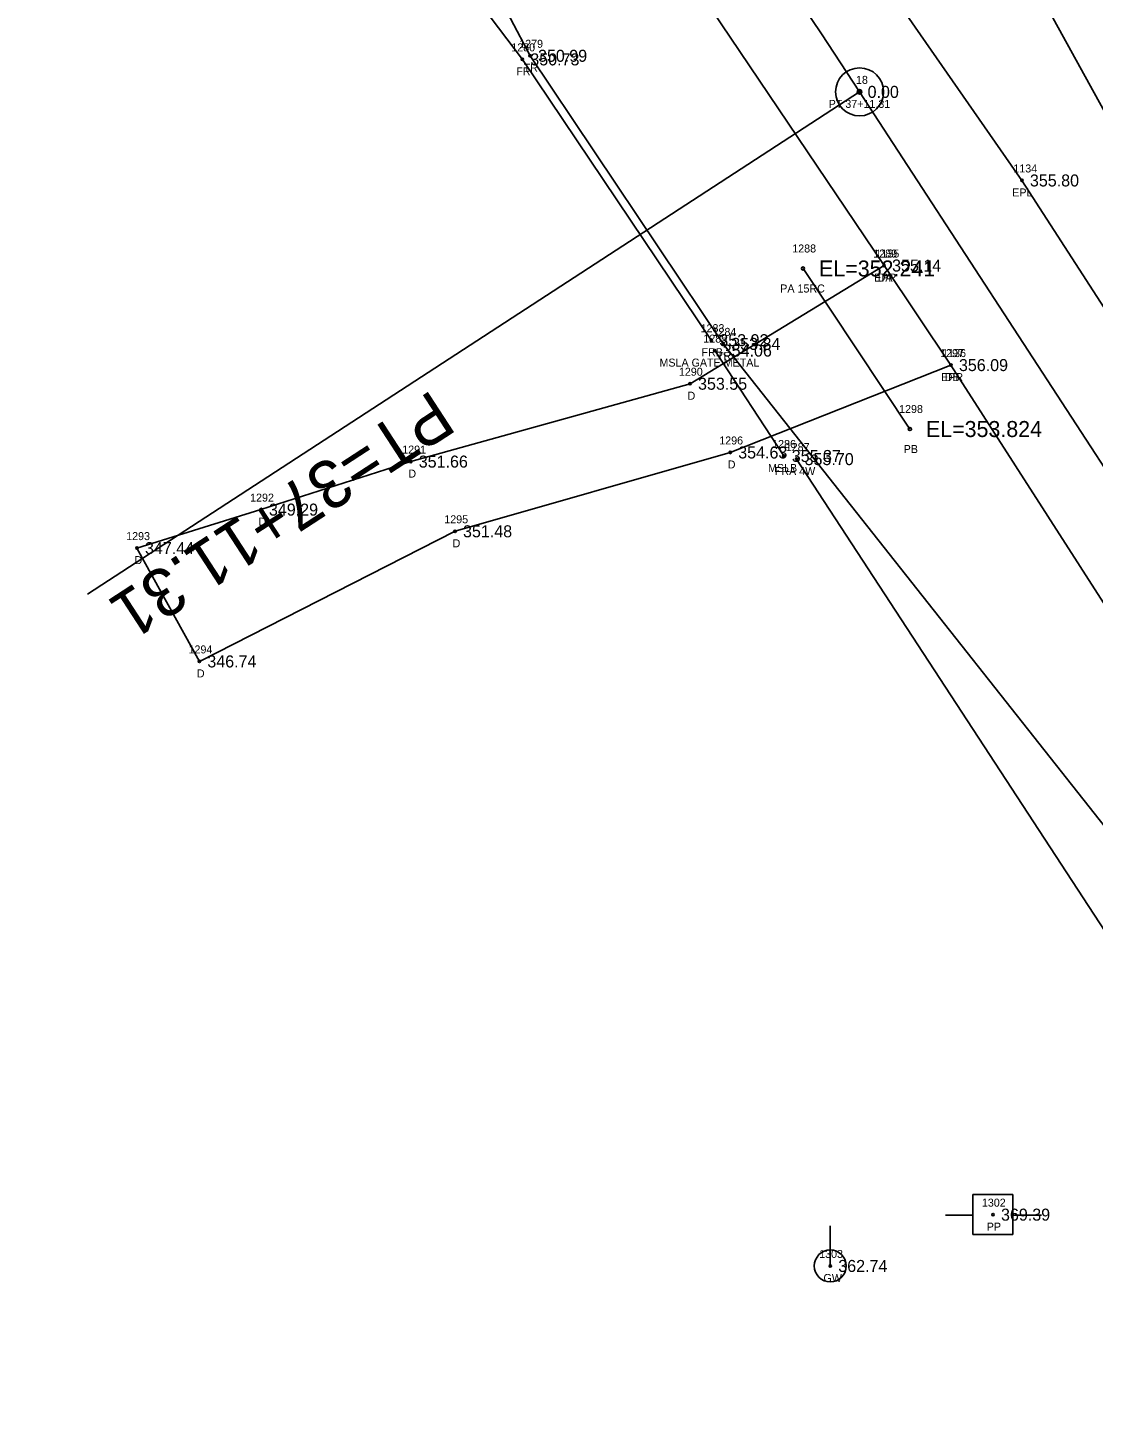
# Model space of a CAD drawing. Extents: x 2006517 to 2008868, y 1001613 to 1004633.
# Drawn here: x 2008072.6 to 2008205.7, y 1002447.7 to 1002622.5 of the extents above; entities that cross this region are included whole.
import ezdxf

# ---------------------------------------------------------------- set-up
doc = ezdxf.new("R2010")
doc.units = 0
for name, color, linetype in [('RD_EX_DR_Pipe', 7, 'Continuous'), ('RD_EX_DR_Pipe_txCode', 7, 'Continuous'), ('RD_EX_Driveway', 7, 'Continuous'), ('RD_EX_Driveway_txCode', 7, 'Continuous'), ('RD_EX_Fence_Other', 7, 'Continuous'), ('RD_EX_Fence_Other_txCode', 7, 'Continuous'), ('RD_EX_Misc', 7, 'Continuous'), ('RD_EX_Misc_txCode', 7, 'Continuous'), ('RD_EX_Road', 7, 'Continuous'), ('RD_EX_Road_txCode', 7, 'Continuous'), ('RD_EX_TX_Driveway_ELEV', 7, 'Continuous'), ('RD_EX_TX_Fence_Other_ELEV', 7, 'Continuous'), ('RD_EX_TX_Misc_ELEV', 7, 'Continuous'), ('RD_EX_TX_Road_ELEV', 7, 'Continuous'), ('RD_EX_TX_UT_ELEV', 7, 'Continuous'), ('RD_EX_TX_VEG_ELEV', 7, 'Continuous'), ('RD_EX_UT', 7, 'Continuous'), ('RD_EX_UT_txCode', 7, 'Continuous'), ('RD_EX_VEG', 7, 'Continuous'), ('RD_EX_VEG_txCode', 7, 'Continuous'), ('RD_HC_Cl', 7, 'Continuous'), ('RD_HC_Data', 7, 'Continuous'), ('RD_HC_Survey_ELEV', 7, 'Continuous'), ('RD_HC_txCode', 7, 'Continuous'), ('RD_SMD_Locator', 7, 'Continuous'), ('RD_TX_Pipe_ElevEX', 7, 'Continuous')]:
    doc.layers.add(name, color=color, linetype=linetype)

msp = doc.modelspace()

# ---------------------------------------------------------------- linework, layer by layer
at = {"layer": 'RD_EX_DR_Pipe'}
msp.add_line((2008169.47, 1002592.48), (2008182.82, 1002572.42), dxfattribs=at)
at = {"layer": 'RD_EX_Driveway'}
msp.add_lwpolyline([(2008179.59, 1002592.85), (2008155.35, 1002578.08), (2008120.46, 1002568.35), (2008101.74, 1002562.35), (2008086.26, 1002557.54), (2008094.05, 1002543.38), (2008125.99, 1002559.64), (2008160.37, 1002569.49), (2008187.94, 1002580.41)], dxfattribs=at)
at = {"layer": 'RD_EX_Fence_Other'}
for points in [[(2007893.11, 1002837.65), (2007909.33, 1002864.32), (2007977.3, 1002793.73), (2008015.3, 1002762.96), (2008043.08, 1002729.4), (2008077.68, 1002692.52), (2008105.37, 1002656.99), (2008134.4, 1002618.61), (2008158.01, 1002583.52)], [(2008168.66, 1002568.66), (2008213.42, 1002500.12), (2008255.13, 1002423.5), (2008299.49, 1002334.35), (2008395.55, 1002139.85)]]:
    msp.add_lwpolyline(points, dxfattribs=at)
at = {"layer": 'RD_EX_Misc'}
msp.add_line((2008158.44, 1002582.22), (2008167.06, 1002569.05), dxfattribs=at)
at = {"layer": 'RD_EX_Road'}
for points in [[(2007926.53, 1002880.46), (2007933.33, 1002888.64), (2008004.37, 1002823.78), (2008041.16, 1002791.39), (2008076.97, 1002755.85), (2008109.64, 1002720.02), (2008140.82, 1002682.03), (2008169.79, 1002642.37), (2008196.81, 1002603.48), (2008249.05, 1002522.64), (2008259.94, 1002505.27), (2008271.29, 1002488.2), (2008299.71, 1002443.6), (2008349.96, 1002366.27), (2008401.09, 1002286.99), (2008453.35, 1002207.39), (2008504.32, 1002128.41), (2008557.14, 1002047.24), (2008604.7, 1001974.22), (2008628.71, 1001937.76), (2008659.22, 1001891.69), (2008712.34, 1001810.72), (2008764.8, 1001729.24), (2008801.79, 1001664.14)], [(2007926.53, 1002880.46), (2007919.41, 1002872.5), (2007991.54, 1002809.35), (2008026.83, 1002776.85), (2008062.37, 1002741.51), (2008093.99, 1002707.06), (2008125.02, 1002669.01), (2008154.41, 1002630.27), (2008179.59, 1002592.85), (2008187.94, 1002580.41), (2008232, 1002511.78), (2008283.05, 1002433.59)]]:
    msp.add_lwpolyline(points, dxfattribs=at)
at = {"layer": 'RD_EX_UT'}
for p, q in [((2008195.69, 1002476.76), (2008190.69, 1002476.76)), ((2008190.69, 1002476.76), (2008190.69, 1002471.76)), ((2008195.69, 1002471.76), (2008195.69, 1002476.76)), ((2008187.26, 1002474.2), (2008190.72, 1002474.2)), ((2008195.61, 1002474.2), (2008199.26, 1002474.2)), ((2008172.87, 1002467.84), (2008172.87, 1002472.84)), ((2008190.69, 1002471.76), (2008195.69, 1002471.76))]:
    msp.add_line(p, q, dxfattribs=at)
msp.add_circle((2008172.87, 1002467.84), 2, dxfattribs=at)
at = {"layer": 'RD_EX_VEG'}
for points in [[(2007395.89, 1003327.12), (2007429.8, 1003285.17), (2007467.04, 1003247.92), (2007498.61, 1003210.85), (2007670.4, 1003045.37), (2007967.56, 1002793.96), (2008054.61, 1002736.66), (2008078.76, 1002693.39), (2008113.28, 1002661.09), (2008135.36, 1002619.06), (2008159.5, 1002583.06), (2008222.5, 1002503.36), (2008272.84, 1002426.91), (2008323.43, 1002347.7), (2008431.42, 1002192), (2008479.95, 1002108.23), (2008533.09, 1002033.28), (2008631.97, 1001873.89), (2008775.08, 1001653.06)], [(2007473.93, 1003322.69), (2007503.07, 1003282.99), (2007540.25, 1003252.05), (2007579.27, 1003219.13), (2007642.18, 1003150.48), (2007952.5, 1002910.4), (2008017.59, 1002836.73), (2008047.98, 1002799.05), (2008087.42, 1002767.09), (2008121.48, 1002729.06), (2008151.49, 1002690.42), (2008185.86, 1002650.76), (2008208.76, 1002609.15), (2008254.04, 1002533.01), (2008311.38, 1002450.28), (2008360.35, 1002372.97), (2008409.06, 1002292.02), (2008460.63, 1002215.28), (2008512.48, 1002133.62), (2008564.88, 1002053.16), (2008614.62, 1001980.71), (2008661.43, 1001938.2)]]:
    msp.add_lwpolyline(points, dxfattribs=at)
at = {"layer": 'RD_HC_Cl'}
msp.add_line((2008176.53, 1002614.55), (2008756.2, 1001724.02), dxfattribs=at)
msp.add_arc((2007371.33, 1002090.43), 960.75, 33.06116, 49.57273, dxfattribs=at)
at = {"layer": 'RD_HC_Data'}
msp.add_line((2008176.53, 1002614.55), (2008080.08, 1002551.77), dxfattribs=at)
for radius in [3, 0.282]:
    msp.add_circle((2008176.53, 1002614.55), radius, dxfattribs=at)
at = {"layer": 'RD_SMD_Locator'}
for centre, radius in [((2008134.4, 1002618.61), 0.15), ((2008135.36, 1002619.06), 0.15), ((2008176.53, 1002614.55), 0.15), ((2008196.81, 1002603.48), 0.15), ((2008169.47, 1002592.48), 0.2), ((2008179.59, 1002592.85), 0.15), ((2008179.59, 1002592.85), 0.15), ((2008158.01, 1002583.52), 0.15), ((2008158.44, 1002582.22), 0.15), ((2008159.5, 1002583.06), 0.15), ((2008187.94, 1002580.41), 0.15), ((2008187.94, 1002580.41), 0.15), ((2008155.35, 1002578.08), 0.15), ((2008182.82, 1002572.42), 0.2), ((2008120.46, 1002568.35), 0.15), ((2008160.37, 1002569.49), 0.15), ((2008167.06, 1002569.05), 0.15), ((2008168.66, 1002568.66), 0.15), ((2008101.74, 1002562.35), 0.15), ((2008125.99, 1002559.64), 0.15), ((2008086.26, 1002557.54), 0.15), ((2008094.05, 1002543.38), 0.15), ((2008193.2, 1002474.25), 0.15), ((2008172.87, 1002467.84), 0.15)]:
    msp.add_circle(centre, radius, dxfattribs=at)

# ---------------------------------------------------------------- texts
at = {"layer": 'RD_EX_DR_Pipe_txCode'}
for s, p in [('1288', (2008168.12, 1002594.48)), ('PA 15RC', (2008166.62, 1002589.48)), ('1298', (2008181.47, 1002574.42)), ('PB', (2008182.04, 1002569.42))]:
    msp.add_text(s, height=1, dxfattribs=at).set_placement(p)
at = {"layer": 'RD_EX_Driveway_txCode'}
for s, p in [('1289', (2008178.24, 1002593.85)), ('DA', (2008178.79, 1002590.85)), ('1297', (2008186.59, 1002581.41)), ('1290', (2008153.96, 1002579.08)), ('DB', (2008187.16, 1002578.41)), ('D', (2008155.04, 1002576.08)), ('1296', (2008159, 1002570.49)), ('1291', (2008119.4, 1002569.35)), ('D', (2008160.06, 1002567.49)), ('D', (2008120.16, 1002566.35)), ('1292', (2008100.39, 1002563.35)), ('D', (2008101.43, 1002560.35)), ('1295', (2008124.65, 1002560.64)), ('1293', (2008084.91, 1002558.54)), ('D', (2008125.69, 1002557.64)), ('D', (2008085.95, 1002555.54)), ('1294', (2008092.7, 1002544.38)), ('D', (2008093.74, 1002541.38))]:
    msp.add_text(s, height=1, dxfattribs=at).set_placement(p)
at = {"layer": 'RD_EX_Fence_Other_txCode'}
for s, p in [('1280', (2008133.02, 1002619.61)), ('FR', (2008133.65, 1002616.61)), ('1283', (2008156.67, 1002584.52)), ('FRB', (2008156.78, 1002581.52)), ('1287', (2008167.31, 1002569.66)), ('FRA 4W', (2008165.94, 1002566.66))]:
    msp.add_text(s, height=1, dxfattribs=at).set_placement(p)
at = {"layer": 'RD_EX_Misc_txCode'}
for s, p in [('1285', (2008157.01, 1002583.22)), ('MSLA GATE METAL', (2008151.53, 1002580.22)), ('1286', (2008165.61, 1002570.05)), ('MSLB', (2008165.09, 1002567.05))]:
    msp.add_text(s, height=1, dxfattribs=at).set_placement(p)
at = {"layer": 'RD_EX_Road_txCode'}
for s, p in [('1134', (2008195.74, 1002604.48)), ('EPL', (2008195.6, 1002601.48)), ('1135', (2008178.52, 1002593.85)), ('EPR', (2008178.36, 1002590.85)), ('1136', (2008186.85, 1002581.41)), ('EPR', (2008186.71, 1002578.41))]:
    msp.add_text(s, height=1, dxfattribs=at).set_placement(p)
at = {"layer": 'RD_EX_TX_Driveway_ELEV'}
for s, p in [('355.14', (2008180.59, 1002592.1)), ('356.09', (2008188.94, 1002579.66)), ('353.55', (2008156.35, 1002577.33)), ('354.63', (2008161.37, 1002568.74)), ('351.66', (2008121.46, 1002567.6)), ('349.29', (2008102.74, 1002561.6)), ('351.48', (2008126.99, 1002558.89)), ('347.44', (2008087.26, 1002556.79)), ('346.74', (2008095.05, 1002542.63))]:
    msp.add_text(s, height=1.5, dxfattribs=at).set_placement(p)
at = {"layer": 'RD_EX_TX_Fence_Other_ELEV'}
for s, p in [('350.73', (2008135.4, 1002617.86)), ('353.92', (2008159.01, 1002582.77)), ('355.70', (2008169.66, 1002567.91))]:
    msp.add_text(s, height=1.5, dxfattribs=at).set_placement(p)
at = {"layer": 'RD_EX_TX_Misc_ELEV'}
for s, p in [('354.06', (2008159.44, 1002581.47)), ('355.37', (2008168.06, 1002568.3))]:
    msp.add_text(s, height=1.5, dxfattribs=at).set_placement(p)
at = {"layer": 'RD_EX_TX_Road_ELEV'}
for s, p in [('355.80', (2008197.81, 1002602.73)), ('355.14', (2008180.59, 1002592.1)), ('356.09', (2008188.94, 1002579.66))]:
    msp.add_text(s, height=1.5, dxfattribs=at).set_placement(p)
at = {"layer": 'RD_EX_TX_UT_ELEV'}
msp.add_text('362.74', height=1.5, dxfattribs=at).set_placement((2008173.87, 1002467.09))
at = {"layer": 'RD_EX_TX_VEG_ELEV'}
for s, p in [('350.99', (2008136.36, 1002618.31)), ('353.84', (2008160.5, 1002582.31))]:
    msp.add_text(s, height=1.5, dxfattribs=at).set_placement(p)
at = {"layer": 'RD_EX_UT_txCode'}
for s, p in [('1302', (2008191.81, 1002475.25)), ('PP', (2008192.42, 1002472.25)), ('1303', (2008171.48, 1002468.84)), ('GW', (2008172.02, 1002465.84))]:
    msp.add_text(s, height=1, dxfattribs=at).set_placement(p)
at = {"layer": 'RD_EX_VEG_txCode'}
for s, p in [('1279', (2008134.01, 1002620.06)), ('TR', (2008134.56, 1002617.06)), ('1284', (2008158.16, 1002584.06)), ('TR', (2008158.71, 1002581.06))]:
    msp.add_text(s, height=1, dxfattribs=at).set_placement(p)
at = {"layer": 'RD_HC_Data'}
msp.add_text('PT=37+11.31', height=6, rotation=213.0612, dxfattribs=at).set_placement((2008123.15, 1002577.42))
at = {"layer": 'RD_HC_Survey_ELEV'}
for s, p in [('0.00', (2008177.53, 1002613.8)), ('369.39', (2008194.2, 1002473.5))]:
    msp.add_text(s, height=1.5, dxfattribs=at).set_placement(p)
at = {"layer": 'RD_HC_txCode'}
for s, p in [('18', (2008176.08, 1002615.55)), ('PT 37+11.31', (2008172.67, 1002612.55))]:
    msp.add_text(s, height=1, dxfattribs=at).set_placement(p)
at = {"layer": 'RD_TX_Pipe_ElevEX'}
for s, p in [('EL=352.241', (2008171.47, 1002591.48)), ('EL=353.824', (2008184.82, 1002571.42))]:
    msp.add_text(s, height=2, dxfattribs=at).set_placement(p)

doc.saveas('drawing.dxf')
